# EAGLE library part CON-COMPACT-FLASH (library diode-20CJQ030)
Various Compact Flash Card Connectors from AVX and Hirose
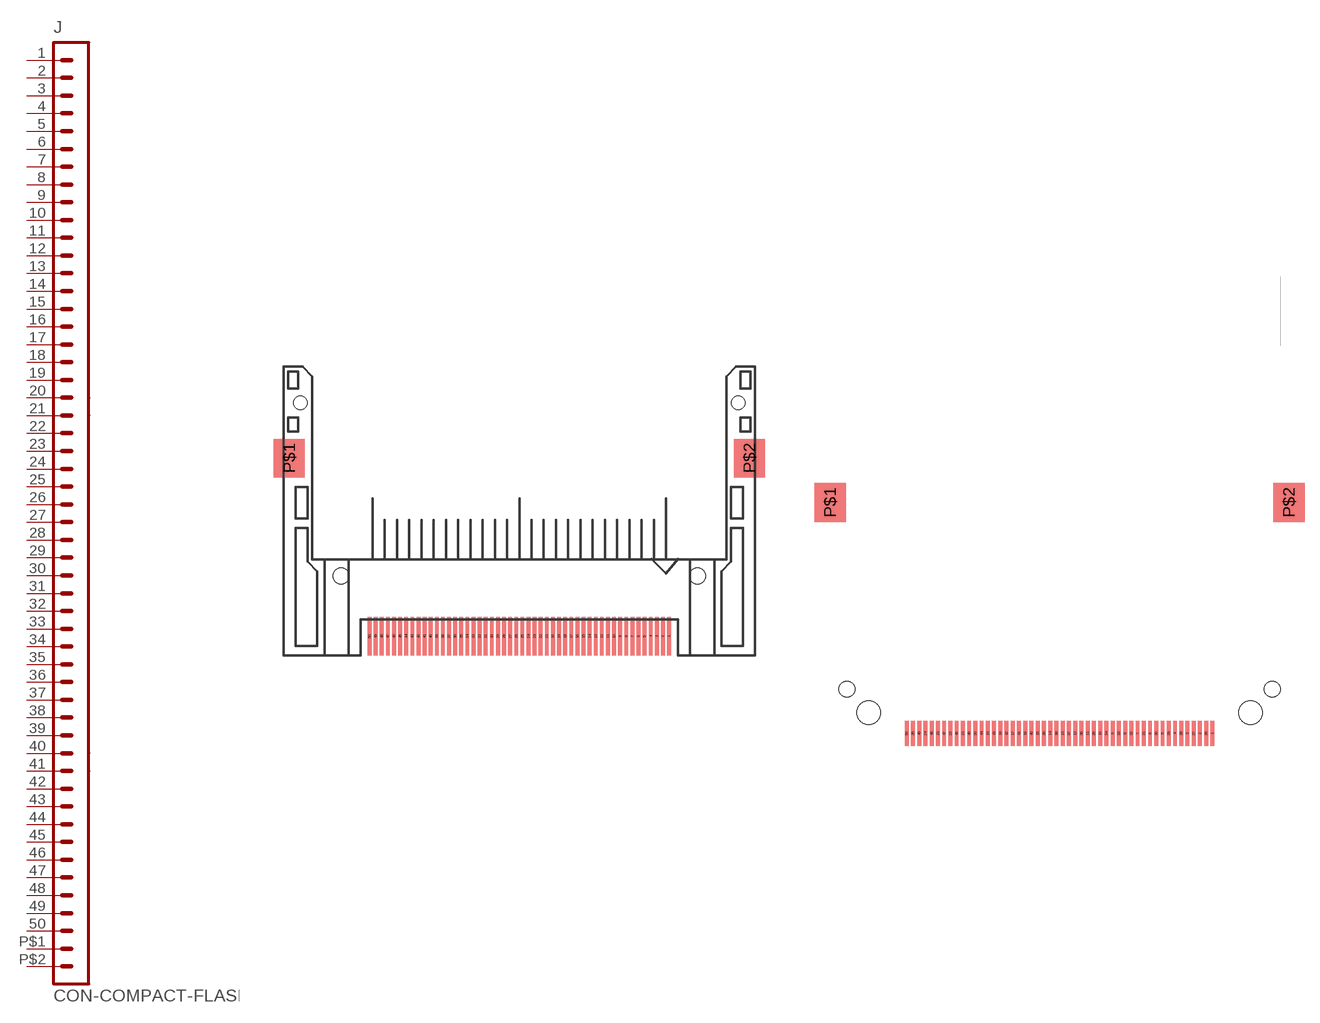
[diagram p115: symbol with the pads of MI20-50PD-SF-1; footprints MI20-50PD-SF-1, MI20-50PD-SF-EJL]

Designator prefix J

## CON-COMPACT-FLASH-1  [MI20-50PD-SF-1]
1  1  pas
2  2  pas
3  3  pas
4  4  pas
5  5  pas
6  6  pas
7  7  pas
8  8  pas
9  9  pas
10  10  pas
11  11  pas
12  12  pas
13  13  pas
14  14  pas
15  15  pas
16  16  pas
17  17  pas
18  18  pas
19  19  pas
20  20  pas
21  21  pas
22  22  pas
23  23  pas
24  24  pas
25  25  pas
26  26  pas
27  27  pas
28  28  pas
29  29  pas
30  30  pas
31  31  pas
32  32  pas
33  33  pas
34  34  pas
35  35  pas
36  36  pas
37  37  pas
38  38  pas
39  39  pas
40  40  pas
41  41  pas
42  42  pas
43  43  pas
44  44  pas
45  45  pas
46  46  pas
47  47  pas
48  48  pas
49  49  pas
50  50  pas
P$1  51  pas
P$2  52  pas

## CON-COMPACT-FLASH-2  [MI20-50PD-SF-EJL]
Pads as for MI20-50PD-SF-1

## CON-COMPACT-FLASH-3  [MI20-50PD-SF-EJR]
Pads as for MI20-50PD-SF-1

## Footprint MI20-50PD-SF-1 (pad centres in mm)
Hirose's MI20-50PD-SF Compact Flash Card Connectors Features: Compact design occupies minimum space Connectors are designed with small width and depth for miniaturization and the foot print on the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
smd 0.4 x 4: 1 15.557,-18.495; 2 14.922,-18.495; 3 14.287,-18.495; 4 13.652,-18.495; 5 13.018,-18.495; 6 12.383,-18.495; 7 11.748,-18.495; 8 11.113,-18.495; 9 10.477,-18.495; 10 9.842,-18.495; 11 9.207,-18.495; 12 8.572,-18.495; 13 7.938,-18.495; 14 7.303,-18.495; 15 6.668,-18.495; 16 6.032,-18.495; 17 5.397,-18.495; 18 4.763,-18.495; 19 4.128,-18.495; 20 3.493,-18.495; 21 2.857,-18.495; 22 2.223,-18.495; 23 1.587,-18.495; 24 0.953,-18.495; 25 0.318,-18.495; 26 -0.318,-18.495; 27 -0.953,-18.495; 28 -1.587,-18.495; 29 -2.223,-18.495; 30 -2.857,-18.495; 31 -3.493,-18.495; 32 -4.128,-18.495; 33 -4.763,-18.495; 34 -5.397,-18.495; 35 -6.032,-18.495; 36 -6.668,-18.495; 37 -7.303,-18.495; 38 -7.938,-18.495; 39 -8.572,-18.495; 40 -9.207,-18.495; 41 -9.842,-18.495; 42 -10.477,-18.495; 43 -11.113,-18.495; 44 -11.748,-18.495; 45 -12.383,-18.495; 46 -13.018,-18.495; 47 -13.652,-18.495; 48 -14.287,-18.495; 49 -14.922,-18.495; 50 -15.557,-18.495
smd 3.2 x 4: P$1 -23.9,0; P$2 23.9,0
hole 1.676 at 18.5,-12.25
hole 1.676 at -18.5,-12.25
hole 1.422 at -22.75,5.75
hole 1.422 at 22.75,5.75

## Footprint MI20-50PD-SF-EJL (pad centres in mm)
Hirose's MI20-50PD-SF-EJL Compact Flash Card Connectors Features: Compact design occupies minimum space Connectors are designed with small width and depth for miniaturization and the foot print on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
smd 0.4 x 2.5: 1 15.557,-23.495; 2 14.287,-23.495; 3 13.018,-23.495; 4 11.748,-23.495; 5 10.477,-23.495; 6 9.207,-23.495; 7 7.938,-23.495; 8 6.668,-23.495; 9 5.397,-23.495; 10 4.128,-23.495; 11 2.857,-23.495; 12 1.587,-23.495; 13 0.318,-23.495; 14 -0.953,-23.495; 15 -2.223,-23.495; 16 -3.493,-23.495; 17 -4.763,-23.495; 18 -6.032,-23.495; 19 -7.303,-23.495; 20 -8.572,-23.495; 21 -9.842,-23.495; 22 -11.113,-23.495; 23 -12.383,-23.495; 24 -13.652,-23.495; 25 -14.922,-23.495; 26 14.922,-23.495; 27 13.652,-23.495; 28 12.383,-23.495; 29 11.113,-23.495; 30 9.842,-23.495; 31 8.572,-23.495; 32 7.303,-23.495; 33 6.032,-23.495; 34 4.763,-23.495; 35 3.493,-23.495; 36 2.223,-23.495; 37 0.953,-23.495; 38 -0.318,-23.495; 39 -1.587,-23.495; 40 -2.857,-23.495; 41 -4.128,-23.495; 42 -5.397,-23.495; 43 -6.668,-23.495; 44 -7.938,-23.495; 45 -9.207,-23.495; 46 -10.477,-23.495; 47 -11.748,-23.495; 48 -13.018,-23.495; 49 -14.287,-23.495; 50 -15.557,-23.495
smd 3.2 x 4: P$1 -23.35,0; P$2 23.35,0
hole 2.4 at -19.45,-21.4
hole 2.4 at 19.45,-21.4
hole 1.6 at -21.65,-19
hole 1.6 at 21.65,-19

## Footprint MI20-50PD-SF-EJR (pad centres in mm)
Hirose's MI20-50PD-SF-EJR Compact Flash Card Connectors Features: Compact design occupies minimum space Connectors are designed with small width and depth for miniaturization and the foot print on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
smd 0.4 x 2.5: 1 15.557,-23.495; 2 14.287,-23.495; 3 13.018,-23.495; 4 11.748,-23.495; 5 10.477,-23.495; 6 9.207,-23.495; 7 7.938,-23.495; 8 6.668,-23.495; 9 5.397,-23.495; 10 4.128,-23.495; 11 2.857,-23.495; 12 1.587,-23.495; 13 0.318,-23.495; 14 -0.953,-23.495; 15 -2.223,-23.495; 16 -3.493,-23.495; 17 -4.763,-23.495; 18 -6.032,-23.495; 19 -7.303,-23.495; 20 -8.572,-23.495; 21 -9.842,-23.495; 22 -11.113,-23.495; 23 -12.383,-23.495; 24 -13.652,-23.495; 25 -14.922,-23.495; 26 14.922,-23.495; 27 13.652,-23.495; 28 12.383,-23.495; 29 11.113,-23.495; 30 9.842,-23.495; 31 8.572,-23.495; 32 7.303,-23.495; 33 6.032,-23.495; 34 4.763,-23.495; 35 3.493,-23.495; 36 2.223,-23.495; 37 0.953,-23.495; 38 -0.318,-23.495; 39 -1.587,-23.495; 40 -2.857,-23.495; 41 -4.128,-23.495; 42 -5.397,-23.495; 43 -6.668,-23.495; 44 -7.938,-23.495; 45 -9.207,-23.495; 46 -10.477,-23.495; 47 -11.748,-23.495; 48 -13.018,-23.495; 49 -14.287,-23.495; 50 -15.557,-23.495
smd 3.2 x 4: P$1 -23.35,0; P$2 23.35,0
hole 2.4 at -19.45,-21.4
hole 2.4 at 19.45,-21.4
hole 1.6 at -21.65,-19
hole 1.6 at 21.65,-19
